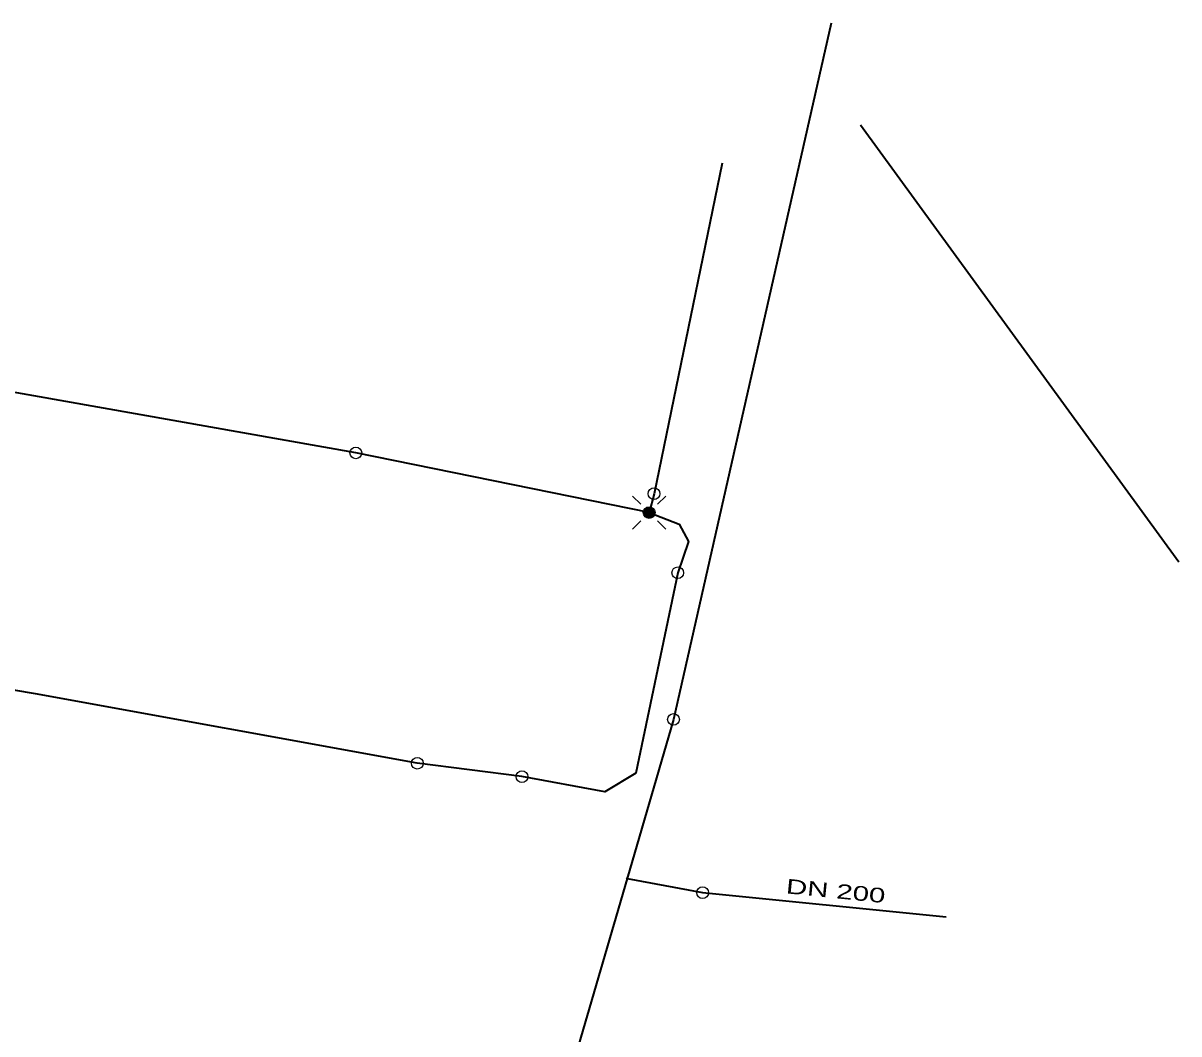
# Model space of a CAD drawing. Extents: x -875105 to -874230, y -1056050 to -1055587.
# Drawn here: x -874427.3 to -874229.9, y -1055759.4 to -1055586.7 of the extents above; entities that cross this region are included whole.
import ezdxf
from ezdxf.enums import TextEntityAlignment as Align

# ---------------------------------------------------------------- set-up
doc = ezdxf.new("R2010")
doc.units = 0
doc.header["$LTSCALE"] = 0.52
doc.layers.add('26', color=7, linetype='Continuous', lineweight=35)
doc.layers.add('30', color=7, linetype='Continuous', lineweight=25)
doc.layers.add('42', color=7, linetype='Continuous')

msp = doc.modelspace()

# ---------------------------------------------------------------- hatches: boundary and pattern name
at = {"layer": '30'}
msp.add_hatch(color=256, dxfattribs=at).paths.add_polyline_path([(-874319.361, -1055670.29, 1), (-874321.361, -1055670.29, 1)])

# ---------------------------------------------------------------- linework, layer by layer
at = {"layer": '26'}
for p, q in [((-874289.283, -1055586.675), (-874316.203, -1055705.634)), ((-874284.289, -1055604.071), (-874229.883, -1055678.692)), ((-874307.886, -1055610.62), (-874319.529, -1055667.067)), ((-874320.361, -1055670.29), (-874370.467, -1055660.102)), ((-874319.529, -1055667.067), (-874320.361, -1055670.29)), ((-874316.203, -1055705.634), (-874324.137, -1055732.825)), ((-874342.087, -1055715.406), (-874359.968, -1055713.119)), ((-874324.137, -1055732.825), (-874352.599, -1055830.364)), ((-874324.137, -1055732.825), (-874311.234, -1055735.224)), ((-874311.234, -1055735.224), (-874269.639, -1055739.361))]:
    msp.add_line(p, q, dxfattribs=at)
for points in [[(-874370.467, -1055660.102), (-874469.607, -1055642.541), (-874511.629, -1055634.673), (-874553.125, -1055627.47), (-874554.11, -1055627.296)], [(-874320.361, -1055670.29), (-874315.261, -1055672.29), (-874313.665, -1055675.238), (-874315.475, -1055680.581)], [(-874359.968, -1055713.119), (-874425.192, -1055701.239), (-874475.352, -1055692.767), (-874543.436, -1055680.45), (-874566.509, -1055676.373), (-874584.243, -1055673.31)], [(-874315.475, -1055680.581), (-874322.632, -1055714.794), (-874327.914, -1055717.987), (-874342.087, -1055715.406)]]:
    msp.add_lwpolyline(points, dxfattribs=at)
at = {"layer": '30'}
for p, q in [((-874321.775, -1055668.875), (-874323.189, -1055667.462)), ((-874318.946, -1055668.875), (-874317.533, -1055667.462)), ((-874321.775, -1055671.704), (-874323.189, -1055673.118)), ((-874318.946, -1055671.704), (-874317.533, -1055673.118))]:
    msp.add_line(p, q, dxfattribs=at)
for centre in [(-874370.467, -1055660.102), (-874319.529, -1055667.067), (-874320.361, -1055670.29), (-874315.475, -1055680.581), (-874316.203, -1055705.634), (-874359.968, -1055713.119), (-874342.087, -1055715.406), (-874311.234, -1055735.224)]:
    msp.add_circle(centre, 1, dxfattribs=at)
at = {"layer": '30', "lineweight": 13}
for radius in [0.15, 0.075]:
    msp.add_circle((-874324.1373, -1055732.8249), radius, dxfattribs=at)

# ---------------------------------------------------------------- texts
at = {"layer": '42', "width": 1.5}
msp.add_text('DN 200', height=2.5, rotation=354.32, dxfattribs=at).set_placement((-874288.6157, -1055736.1737), align=Align.CENTER)

doc.saveas('drawing.dxf')
